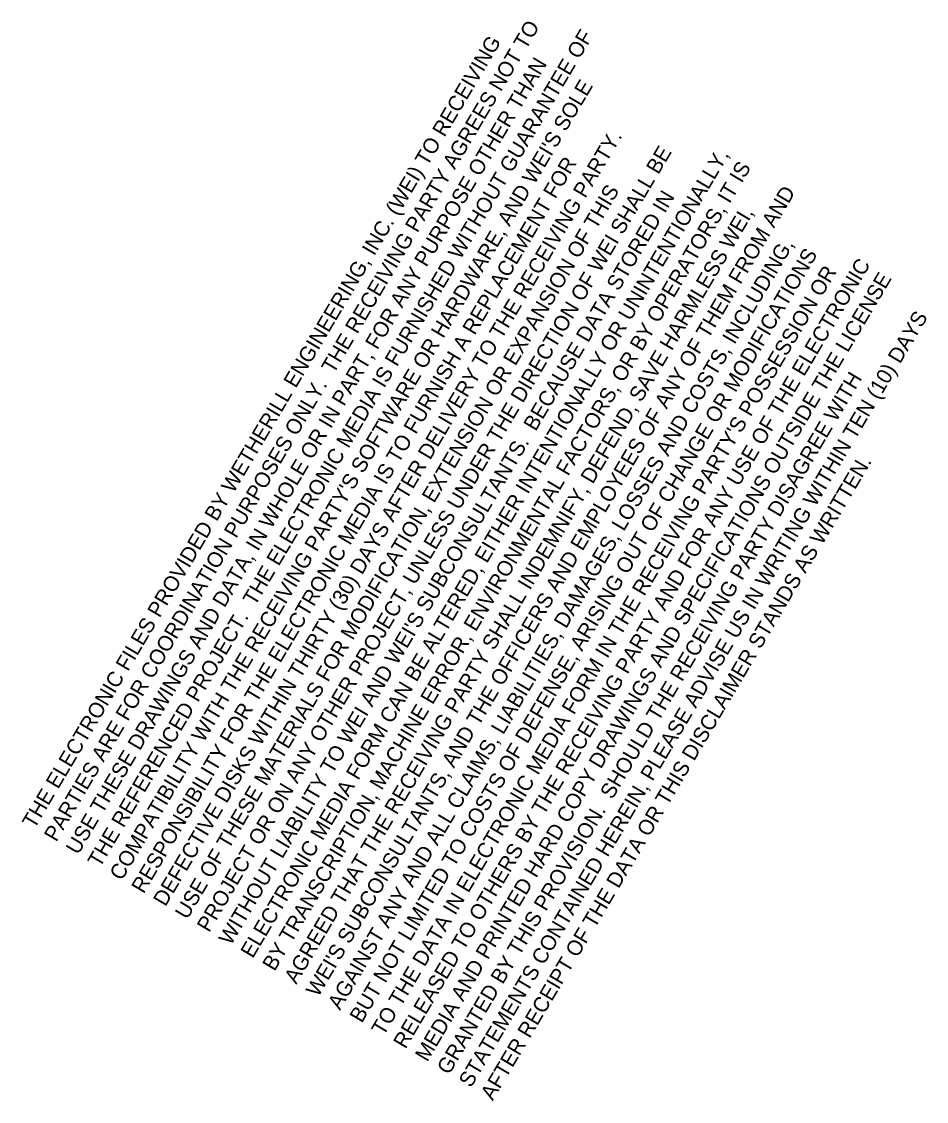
# Model space of a CAD drawing. Extents: x 2138032 to 2141442, y 405316 to 410985.
# Drawn here: x 2138032 to 2139383, y 405316 to 406928 of the extents above; entities that cross this region are included whole.
import ezdxf

# ---------------------------------------------------------------- set-up
doc = ezdxf.new("R2010")
doc.units = 0
doc.layers.add('Default', color=7, linetype='Continuous')

msp = doc.modelspace()

# ---------------------------------------------------------------- texts
at = {"layer": 'Default'}
for s, p in [('PARTIES ARE FOR COORDINATION PURPOSES ONLY.  THE RECEIVING PARTY AGREES NOT TO ', (2138083.7, 405702.1)), ('THE REFERENCED PROJECT.  THE ELECTRONIC MEDIA IS FURNISHED WITHOUT GUARANTEE OF ', (2138148.9, 405663.5)), ('THE ELECTRONIC FILES PROVIDED BY WETHERILL ENGINEERING, INC. (WEI) TO RECEIVING ', (2138051.1, 405721.4)), ('USE THESE DRAWINGS AND DATA, IN WHOLE OR IN PART, FOR ANY PURPOSE OTHER THAN ', (2138116.3, 405682.8)), ("COMPATIBILITY WITH THE RECEIVING PARTY'S SOFTWARE OR HARDWARE, AND WEI'S SOLE ", (2138181.5, 405644.1)), ('DEFECTIVE DISKS WITHIN THIRTY (30) DAYS AFTER DELIVERY TO THE RECEIVING PARTY.  ', (2138246.7, 405605.5)), ('PROJECT OR ON ANY OTHER PROJECT, UNLESS UNDER THE DIRECTION OF WEI SHALL BE ', (2138311.9, 405566.9)), ('RESPONSIBILITY FOR THE ELECTRONIC MEDIA IS TO FURNISH A REPLACEMENT FOR ', (2138214.1, 405624.8)), ('ELECTRONIC MEDIA FORM CAN BE ALTERED, EITHER INTENTIONALLY OR UNINTENTIONALLY, ', (2138377.1, 405528.2)), ('BY TRANSCRIPTION, MACHINE ERROR, ENVIRONMENTAL FACTORS, OR BY OPERATORS, IT IS ', (2138409.7, 405508.9)), ('USE OF THESE MATERIALS FOR MODIFICATION, EXTENSION OR EXPANSION OF THIS ', (2138279.3, 405586.2)), ("WITHOUT LIABILITY TO WEI AND WEI'S SUBCONSULTANTS.  BECAUSE DATA STORED IN ", (2138344.5, 405547.5)), ("WEI'S SUBCONSULTANTS, AND THE OFFICERS AND EMPLOYEES OF ANY OF THEM FROM AND ", (2138474.8, 405470.3)), ('AGREED THAT THE RECEIVING PARTY SHALL INDEMNIFY, DEFEND, SAVE HARMLESS WEI, ', (2138442.2, 405489.6)), ('AGAINST ANY AND ALL CLAIMS, LIABILITIES, DAMAGES, LOSSES AND COSTS, INCLUDING, ', (2138507.4, 405450.9)), ('BUT NOT LIMITED TO COSTS OF DEFENSE, ARISING OUT OF CHANGE OR MODIFICATIONS ', (2138540, 405431.6)), ("TO THE DATA IN ELECTRONIC MEDIA FORM IN THE RECEIVING PARTY'S POSSESSION OR ", (2138572.6, 405412.3)), ('RELEASED TO OTHERS BY THE RECEIVING PARTY AND FOR ANY USE OF THE ELECTRONIC ', (2138605.2, 405393)), ('MEDIA AND PRINTED HARD COPY DRAWINGS AND SPECIFICATIONS OUTSIDE THE LICENSE ', (2138637.8, 405373.6)), ('STATEMENTS CONTAINED HEREIN, PLEASE ADVISE US IN WRITING WITHIN TEN (10) DAYS ', (2138703, 405335)), ('GRANTED BY THIS PROVISION.  SHOULD THE RECEIVING PARTY DISAGREE WITH ', (2138670.4, 405354.3)), ('AFTER RECEIPT OF THE DATA OR THIS DISCLAIMER STANDS AS WRITTEN.', (2138735.6, 405315.7))]:
    msp.add_text(s, height=22.733, rotation=59.3391, dxfattribs=at).set_placement(p)

doc.saveas('drawing.dxf')
